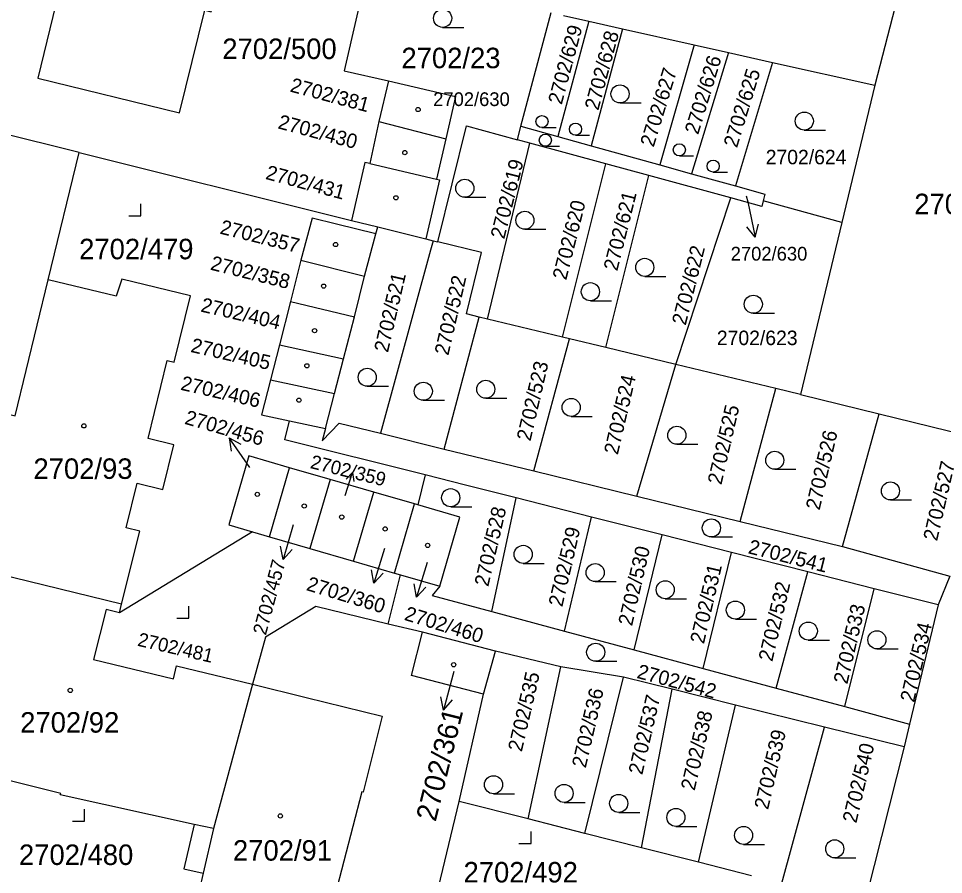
# Model space of a CAD drawing. Extents: x -496682 to -495776, y -1088797 to -1088018.
# Drawn here: x -496634.1 to -496557.4, y -1088522.6 to -1088451.6 of the extents above; entities that cross this region are included whole.
import ezdxf

# ---------------------------------------------------------------- set-up
doc = ezdxf.new("R2010")
doc.units = 0
for name, color, linetype in [('Hranice parcel', 7, 'Continuous'), ('Parcelní čísla', 7, 'Continuous'), ('Pop  PČ popisy', 7, 'Continuous'), ('Vnitřní kresba', 7, 'Continuous'), ('Značky budov', 7, 'Continuous'), ('Značky kultur', 7, 'Continuous')]:
    doc.layers.add(name, color=color, linetype=linetype)

msp = doc.modelspace()

# ---------------------------------------------------------------- linework, layer by layer
at = {"layer": 'Hranice parcel'}
for p, q in [((-496560.5, -1088447.06), (-496563.11, -1088457.17)), ((-496592.45, -1088460.57), (-496589.94, -1088451.12)), ((-496586.83, -1088451.86), (-496589.39, -1088461.42)), ((-496588.92, -1088451.39), (-496586.83, -1088451.86)), ((-496586.83, -1088451.86), (-496584.04, -1088452.48)), ((-496584.04, -1088452.48), (-496586.63, -1088462.19)), ((-496584.04, -1088452.48), (-496578.08, -1088453.82)), ((-496578.08, -1088453.82), (-496580.92, -1088463.77)), ((-496578.08, -1088453.82), (-496575.25, -1088454.45)), ((-496575.25, -1088454.45), (-496578.3, -1088464.51)), ((-496575.25, -1088454.45), (-496571.59, -1088455.27)), ((-496571.59, -1088455.27), (-496574.67, -1088465.51)), ((-496571.59, -1088455.27), (-496563.11, -1088457.17)), ((-496603.42, -1088456.81), (-496604.23, -1088460.18)), ((-496563.11, -1088457.17), (-496565.84, -1088468.56)), ((-496629.09, -1088462.74), (-496640.95, -1088459.81)), ((-496604.23, -1088460.18), (-496604.99, -1088463.66)), ((-496604.23, -1088460.18), (-496598.69, -1088461.62)), ((-496592.74, -1088461.68), (-496592.45, -1088460.57)), ((-496592.45, -1088460.57), (-496589.39, -1088461.42)), ((-496598.69, -1088461.62), (-496599.45, -1088464.96)), ((-496591.72, -1088461.96), (-496592.74, -1088461.68)), ((-496589.39, -1088461.42), (-496586.63, -1088462.19)), ((-496595.21, -1088476.56), (-496591.72, -1088461.96)), ((-496585.42, -1088463.68), (-496591.72, -1088461.96)), ((-496586.63, -1088462.19), (-496580.92, -1088463.77)), ((-496631.65, -1088473.31), (-496629.09, -1088462.74)), ((-496604.99, -1088463.66), (-496599.45, -1088464.96)), ((-496589.01, -1088478.06), (-496585.42, -1088463.68)), ((-496581.84, -1088464.65), (-496585.42, -1088463.68)), ((-496580.92, -1088463.77), (-496578.3, -1088464.51)), ((-496585.4, -1088478.93), (-496581.84, -1088464.65)), ((-496575.06, -1088466.51), (-496581.84, -1088464.65)), ((-496578.3, -1088464.51), (-496574.67, -1088465.51)), ((-496579.62, -1088480.33), (-496575.06, -1088466.51)), ((-496565.84, -1088468.56), (-496572.37, -1088466.76)), ((-496606.49, -1088468.38), (-496604.32, -1088468.92)), ((-496565.84, -1088468.56), (-496569.26, -1088482.83)), ((-496605.41, -1088472.99), (-496604.48, -1088469.49)), ((-496604.48, -1088469.49), (-496604.32, -1088468.92)), ((-496604.32, -1088468.92), (-496600.33, -1088469.91)), ((-496600.33, -1088469.91), (-496599.74, -1088470.06)), ((-496599.74, -1088470.06), (-496599.34, -1088470.16)), ((-496610.7, -1088471.68), (-496611.55, -1088475.11)), ((-496610.7, -1088471.68), (-496605.41, -1088472.99)), ((-496606.26, -1088476.38), (-496605.41, -1088472.99)), ((-496611.55, -1088475.11), (-496612.47, -1088478.69)), ((-496611.55, -1088475.11), (-496606.26, -1088476.38)), ((-496607.16, -1088479.85), (-496606.26, -1088476.38)), ((-496598.81, -1088487.34), (-496595.91, -1088476.39)), ((-496595.21, -1088476.56), (-496595.91, -1088476.39)), ((-496589.01, -1088478.06), (-496595.21, -1088476.56)), ((-496612.47, -1088478.69), (-496613.22, -1088481.59)), ((-496612.47, -1088478.69), (-496607.16, -1088479.85)), ((-496591.38, -1088489.16), (-496588.43, -1088478.2)), ((-496588.43, -1088478.2), (-496589.01, -1088478.06)), ((-496585.4, -1088478.93), (-496588.43, -1088478.2)), ((-496579.62, -1088480.33), (-496585.4, -1088478.93)), ((-496607.91, -1088482.74), (-496607.16, -1088479.85)), ((-496582.83, -1088491.26), (-496579.62, -1088480.33)), ((-496571.31, -1088482.33), (-496579.62, -1088480.33)), ((-496613.22, -1088481.59), (-496607.91, -1088482.74)), ((-496574.26, -1088493.36), (-496571.31, -1088482.33)), ((-496569.26, -1088482.83), (-496571.31, -1088482.33)), ((-496608.66, -1088485.64), (-496607.91, -1088482.74)), ((-496569.26, -1088482.83), (-496562.76, -1088484.43)), ((-496565.8, -1088495.44), (-496562.76, -1088484.43)), ((-496562.76, -1088484.43), (-496553.34, -1088486.74)), ((-496611.65, -1088485), (-496608.66, -1088485.64)), ((-496608.66, -1088485.64), (-496608.93, -1088486.67)), ((-496604.09, -1088486.04), (-496598.81, -1088487.34)), ((-496611.65, -1088488.89), (-496615.02, -1088487.91)), ((-496598.81, -1088487.34), (-496591.38, -1088489.16)), ((-496613.31, -1088494.62), (-496611.65, -1088488.89)), ((-496608.28, -1088489.87), (-496611.65, -1088488.89)), ((-496600.4, -1088489.48), (-496601.01, -1088491.98)), ((-496591.38, -1088489.16), (-496582.83, -1088491.26)), ((-496608.28, -1088489.87), (-496609.94, -1088495.6)), ((-496604.66, -1088490.92), (-496608.28, -1088489.87)), ((-496606.33, -1088496.65), (-496604.66, -1088490.92)), ((-496601.27, -1088491.9), (-496604.66, -1088490.92)), ((-496594.87, -1088500.81), (-496592.84, -1088491.4)), ((-496586.59, -1088492.99), (-496592.84, -1088491.4)), ((-496582.83, -1088491.26), (-496574.26, -1088493.36)), ((-496602.94, -1088497.63), (-496601.27, -1088491.9)), ((-496601.01, -1088491.98), (-496601.27, -1088491.9)), ((-496588.84, -1088502.44), (-496586.59, -1088492.99)), ((-496580.73, -1088494.47), (-496586.59, -1088492.99)), ((-496574.26, -1088493.36), (-496565.8, -1088495.44)), ((-496614.7, -1088494.21), (-496625.74, -1088500.93)), ((-496614.7, -1088494.21), (-496613.31, -1088494.62)), ((-496613.31, -1088494.62), (-496609.94, -1088495.6)), ((-496583.05, -1088504), (-496580.73, -1088494.47)), ((-496574.99, -1088495.93), (-496580.73, -1088494.47)), ((-496609.94, -1088495.6), (-496606.33, -1088496.65)), ((-496565.8, -1088495.44), (-496556.89, -1088497.88)), ((-496577.33, -1088505.54), (-496574.99, -1088495.93)), ((-496568.66, -1088497.54), (-496574.99, -1088495.93)), ((-496606.33, -1088496.65), (-496602.94, -1088497.63)), ((-496625.56, -1088500.2), (-496637.35, -1088497.34)), ((-496603.45, -1088501.86), (-496602.44, -1088497.78)), ((-496602.94, -1088497.63), (-496602.44, -1088497.78)), ((-496602.44, -1088497.78), (-496599.17, -1088498.73)), ((-496571.29, -1088507.17), (-496568.66, -1088497.54)), ((-496563.16, -1088498.94), (-496568.66, -1088497.54)), ((-496556.89, -1088497.88), (-496557.86, -1088500.28)), ((-496599.17, -1088498.73), (-496599.81, -1088499.48)), ((-496599.81, -1088499.48), (-496594.87, -1088500.81)), ((-496565.6, -1088508.71), (-496563.16, -1088498.94)), ((-496557.86, -1088500.28), (-496563.16, -1088498.94)), ((-496625.74, -1088500.93), (-496625.56, -1088500.2)), ((-496594.87, -1088500.81), (-496588.84, -1088502.44)), ((-496557.86, -1088500.28), (-496560.22, -1088510.16)), ((-496600.61, -1088502.54), (-496603.45, -1088501.86)), ((-496594.55, -1088504.11), (-496600.61, -1088502.54)), ((-496588.84, -1088502.44), (-496583.05, -1088504)), ((-496583.05, -1088504), (-496577.33, -1088505.54)), ((-496595.56, -1088507.68), (-496594.55, -1088504.11)), ((-496589.15, -1088505.41), (-496594.55, -1088504.11)), ((-496591.86, -1088518.03), (-496589.15, -1088505.41)), ((-496583.95, -1088506.27), (-496589.15, -1088505.41)), ((-496577.33, -1088505.54), (-496571.29, -1088507.17)), ((-496587.14, -1088519.23), (-496583.95, -1088506.27)), ((-496579.92, -1088507.27), (-496583.95, -1088506.27)), ((-496597.58, -1088516.58), (-496595.56, -1088507.68)), ((-496582.44, -1088520.43), (-496579.92, -1088507.27)), ((-496574.65, -1088508.58), (-496579.92, -1088507.27)), ((-496571.29, -1088507.17), (-496565.6, -1088508.71)), ((-496577.74, -1088521.62), (-496574.65, -1088508.58)), ((-496567.27, -1088510.42), (-496574.65, -1088508.58)), ((-496565.6, -1088508.71), (-496560.22, -1088510.16)), ((-496560.22, -1088510.16), (-496560.68, -1088512.06)), ((-496570.83, -1088523.36), (-496567.27, -1088510.42)), ((-496560.68, -1088512.06), (-496567.27, -1088510.42)), ((-496560.68, -1088512.06), (-496563.91, -1088524.85)), ((-496601.3, -1088532.22), (-496597.58, -1088516.58)), ((-496591.86, -1088518.03), (-496597.58, -1088516.58)), ((-496587.14, -1088519.23), (-496591.86, -1088518.03)), ((-496582.44, -1088520.43), (-496587.14, -1088519.23)), ((-496577.74, -1088521.62), (-496582.44, -1088520.43)), ((-496573.34, -1088522.74), (-496577.74, -1088521.62))]:
    msp.add_line(p, q, dxfattribs=at)
for points in [[(-496627.19, -1088437.45), (-496629.65, -1088447.47), (-496630.27, -1088447.33), (-496632.51, -1088456.57), (-496620.75, -1088459.46), (-496618.65, -1088450.94), (-496618.13, -1088451.06), (-496617.25, -1088447.52), (-496617.78, -1088447.42), (-496615.79, -1088439.35)], [(-496605.08, -1088447.17), (-496607.1, -1088455.97), (-496603.42, -1088456.81)], [(-496603.42, -1088456.81), (-496597.88, -1088458.09), (-496598.69, -1088461.62)], [(-496599.34, -1088470.16), (-496596.95, -1088460.53), (-496592.74, -1088461.68)], [(-496629.09, -1088462.74), (-496607.59, -1088468.1), (-496606.49, -1088468.38)], [(-496604.99, -1088463.66), (-496605.38, -1088463.57), (-496606.49, -1088468.38)], [(-496599.45, -1088464.96), (-496599.21, -1088465.01), (-496600.33, -1088469.91)], [(-496574.67, -1088465.51), (-496572.24, -1088466.19), (-496572.37, -1088466.76)], [(-496572.37, -1088466.76), (-496572.48, -1088467.21), (-496575.06, -1088466.51)], [(-496604.48, -1088469.49), (-496607.73, -1088468.68), (-496609.76, -1088468.18), (-496610.7, -1088471.68)], [(-496599.74, -1088470.06), (-496599.96, -1088470.85), (-496604.09, -1088486.04)], [(-496595.91, -1088476.39), (-496596.96, -1088476.14), (-496595.73, -1088471.05), (-496599.34, -1088470.16)], [(-496637.35, -1088497.34), (-496634.78, -1088486.77), (-496635.48, -1088486.6), (-496634.95, -1088484.46), (-496634.38, -1088484.6), (-496631.65, -1088473.31)], [(-496625.56, -1088500.2), (-496624.06, -1088494.16), (-496625.17, -1088493.89), (-496624.28, -1088490.18), (-496622.15, -1088490.71), (-496621.22, -1088487), (-496623.35, -1088486.47), (-496621.79, -1088479.99), (-496621.21, -1088480.13), (-496619.86, -1088474.64), (-496625.54, -1088473.24), (-496626, -1088474.67), (-496631.65, -1088473.31)], [(-496613.22, -1088481.59), (-496613.97, -1088484.5), (-496611.65, -1088485)], [(-496600.4, -1088489.48), (-496612.03, -1088486.58), (-496611.65, -1088485)], [(-496608.93, -1088486.67), (-496607.51, -1088485.21), (-496604.09, -1088486.04)], [(-496615.02, -1088487.91), (-496616.68, -1088493.64), (-496614.7, -1088494.21)], [(-496592.84, -1088491.4), (-496597.04, -1088490.33), (-496600.4, -1088489.48)], [(-496599.17, -1088498.73), (-496597.51, -1088493), (-496601.01, -1088491.98)], [(-496625.74, -1088500.93), (-496626.84, -1088500.66), (-496627.88, -1088504.8), (-496621.27, -1088506.42), (-496621, -1088505.32), (-496614.7, -1088506.86)], [(-496603.45, -1088501.86), (-496609.45, -1088500.4), (-496613.64, -1088502.94), (-496614.7, -1088506.86)], [(-496595.56, -1088507.68), (-496601.53, -1088506.12), (-496600.61, -1088502.54)], [(-496614.7, -1088506.86), (-496617.94, -1088518.83), (-496619.55, -1088518.48)], [(-496619.55, -1088518.48), (-496630.64, -1088516.04), (-496630.61, -1088515.92), (-496641.69, -1088513.15), (-496641.66, -1088513.05)], [(-496619.55, -1088518.48), (-496620.39, -1088522.17), (-496618.8, -1088522.54), (-496620.02, -1088527.84), (-496620.32, -1088527.76), (-496621.75, -1088533.36)]]:
    msp.add_lwpolyline(points, dxfattribs=at)
at = {"layer": 'Pop  PČ popisy'}
for p, q in [((-496573.77, -1088466.34), (-496573.65, -1088466.84)), ((-496573.65, -1088466.84), (-496573.026, -1088469.775)), ((-496573.026, -1088469.775), (-496572.744, -1088468.692)), ((-496573.026, -1088469.775), (-496573.724, -1088468.9)), ((-496614.93, -1088488.87), (-496616.651, -1088486.412)), ((-496616.651, -1088486.412), (-496615.667, -1088486.945)), ((-496616.651, -1088486.412), (-496616.487, -1088487.519)), ((-496607.03, -1088491.21), (-496606.409, -1088489.298)), ((-496606.409, -1088489.298), (-496606.935, -1088489.832)), ((-496606.409, -1088489.298), (-496606.297, -1088490.04)), ((-496611.34, -1088493.63), (-496612.167, -1088496.515)), ((-496612.167, -1088496.515), (-496612.372, -1088495.414)), ((-496603.77, -1088495.59), (-496604.647, -1088498.46)), ((-496612.167, -1088496.515), (-496611.41, -1088495.69)), ((-496600.23, -1088496.75), (-496601.107, -1088499.62)), ((-496604.647, -1088498.46), (-496604.833, -1088497.356)), ((-496604.647, -1088498.46), (-496603.876, -1088497.649)), ((-496601.107, -1088499.62), (-496601.293, -1088498.516)), ((-496601.107, -1088499.62), (-496600.336, -1088498.809)), ((-496598.1, -1088506.1), (-496598.877, -1088508.999)), ((-496598.02, -1088505.81), (-496598.1, -1088506.1)), ((-496598.877, -1088508.999), (-496599.101, -1088507.902)), ((-496598.877, -1088508.999), (-496598.134, -1088508.161))]:
    msp.add_line(p, q, dxfattribs=at)
at = {"layer": 'Vnitřní kresba'}
for p, q in [((-496614.7, -1088506.86), (-496610.25, -1088507.95)), ((-496610.25, -1088507.95), (-496603.96, -1088509.5)), ((-496603.96, -1088509.5), (-496605.52, -1088515.81)), ((-496605.65, -1088515.77), (-496609.45, -1088530.51)), ((-496605.52, -1088515.81), (-496605.65, -1088515.77)), ((-496617.94, -1088518.83), (-496618.8, -1088522.54))]:
    msp.add_line(p, q, dxfattribs=at)
at = {"layer": 'Značky budov'}
for centre in [(-496600.977, -1088459.179), (-496602.077, -1088462.749), (-496602.817, -1088466.499), (-496607.817, -1088470.379), (-496608.807, -1088473.829), (-496609.557, -1088477.519), (-496610.197, -1088480.439), (-496610.857, -1088483.289), (-496628.687, -1088485.419), (-496614.307, -1088491.099), (-496610.417, -1088492.069), (-496607.307, -1088492.989), (-496603.707, -1088493.969), (-496600.187, -1088495.339), (-496598.027, -1088505.239), (-496629.817, -1088507.369), (-496612.397, -1088517.779)]:
    msp.add_circle(centre, 0.175, dxfattribs=at)
at = {"layer": 'Značky kultur'}
for p, q in [((-496598.943, -1088452.36), (-496597.193, -1088452.36)), ((-496584.233, -1088458.63), (-496582.483, -1088458.63)), ((-496590.705, -1088460.68), (-496589.533, -1088460.68)), ((-496568.953, -1088460.89), (-496567.203, -1088460.89)), ((-496587.925, -1088461.31), (-496586.753, -1088461.31)), ((-496590.425, -1088462.22), (-496589.253, -1088462.22)), ((-496579.315, -1088463.02), (-496578.143, -1088463.02)), ((-496576.505, -1088464.37), (-496575.333, -1088464.37)), ((-496597.103, -1088466.46), (-496595.353, -1088466.46)), ((-496623.96, -1088468.01), (-496623.96, -1088467.01)), ((-496624.961, -1088468.01), (-496623.96, -1088468.01)), ((-496592.123, -1088469.11), (-496590.373, -1088469.11)), ((-496582.183, -1088473.02), (-496580.433, -1088473.02)), ((-496586.693, -1088475.04), (-496584.943, -1088475.04)), ((-496573.183, -1088476.08), (-496571.433, -1088476.08)), ((-496605.193, -1088482.14), (-496603.443, -1088482.14)), ((-496600.543, -1088483.3), (-496598.793, -1088483.3)), ((-496595.363, -1088483.13), (-496593.613, -1088483.13)), ((-496588.283, -1088484.64), (-496586.533, -1088484.64)), ((-496579.523, -1088486.95), (-496577.773, -1088486.95)), ((-496571.403, -1088489.02), (-496569.653, -1088489.02)), ((-496561.813, -1088491.57), (-496560.063, -1088491.57)), ((-496598.273, -1088492.13), (-496596.523, -1088492.13)), ((-496576.663, -1088494.64), (-496574.913, -1088494.64)), ((-496592.263, -1088496.83), (-496590.513, -1088496.83)), ((-496586.293, -1088498.34), (-496584.543, -1088498.34)), ((-496580.483, -1088499.77), (-496578.733, -1088499.77)), ((-496619.98, -1088501.37), (-496619.98, -1088500.37)), ((-496620.981, -1088501.37), (-496619.98, -1088501.37)), ((-496574.673, -1088501.45), (-496572.923, -1088501.45)), ((-496568.623, -1088503.2), (-496566.873, -1088503.2)), ((-496562.933, -1088503.92), (-496561.183, -1088503.92)), ((-496586.253, -1088504.95), (-496584.503, -1088504.95)), ((-496594.723, -1088515.94), (-496592.973, -1088515.94)), ((-496588.873, -1088516.66), (-496587.123, -1088516.66)), ((-496628.63, -1088518.21), (-496628.63, -1088517.21)), ((-496584.343, -1088517.49), (-496582.593, -1088517.49)), ((-496629.631, -1088518.21), (-496628.63, -1088518.21)), ((-496579.603, -1088518.65), (-496577.853, -1088518.65)), ((-496591.61, -1088520.06), (-496591.61, -1088519.06)), ((-496592.611, -1088520.06), (-496591.61, -1088520.06)), ((-496573.993, -1088520.15), (-496572.243, -1088520.15)), ((-496566.433, -1088521.26), (-496564.683, -1088521.26))]:
    msp.add_line(p, q, dxfattribs=at)
for centre, radius in [((-496598.943, -1088451.61), 0.75), ((-496584.233, -1088457.88), 0.75), ((-496568.953, -1088460.14), 0.75), ((-496590.705, -1088460.177), 0.502), ((-496587.925, -1088460.807), 0.502), ((-496590.425, -1088461.717), 0.502), ((-496579.315, -1088462.517), 0.502), ((-496576.505, -1088463.867), 0.502), ((-496597.103, -1088465.71), 0.75), ((-496592.123, -1088468.36), 0.75), ((-496582.183, -1088472.27), 0.75), ((-496586.693, -1088474.29), 0.75), ((-496573.183, -1088475.33), 0.75), ((-496605.193, -1088481.39), 0.75), ((-496600.543, -1088482.55), 0.75), ((-496595.363, -1088482.38), 0.75), ((-496588.283, -1088483.89), 0.75), ((-496579.523, -1088486.2), 0.75), ((-496571.403, -1088488.27), 0.75), ((-496561.813, -1088490.82), 0.75), ((-496598.273, -1088491.38), 0.75), ((-496576.663, -1088493.89), 0.75), ((-496592.263, -1088496.08), 0.75), ((-496586.293, -1088497.59), 0.75), ((-496580.483, -1088499.02), 0.75), ((-496574.673, -1088500.7), 0.75), ((-496568.623, -1088502.45), 0.75), ((-496562.933, -1088503.17), 0.75), ((-496586.253, -1088504.2), 0.75), ((-496594.723, -1088515.19), 0.75), ((-496588.873, -1088515.91), 0.75), ((-496584.343, -1088516.74), 0.75), ((-496579.603, -1088517.9), 0.75), ((-496573.993, -1088519.4), 0.75), ((-496566.433, -1088520.51), 0.75)]:
    msp.add_circle(centre, radius, dxfattribs=at)

# ---------------------------------------------------------------- texts
at = {"layer": 'Parcelní čísla'}
for s, height, rotation, p in [('2702/629', 1.2, 75, (-496589.068, -1088458.825)), ('2702/628', 1.2, 75, (-496586.038, -1088459.305)), ('2702/626', 1.2, 73, (-496577.758, -1088461.315)), ('2702/627', 1.2, 73, (-496581.448, -1088462.355)), ('2702/625', 1.2, 73, (-496574.538, -1088462.415)), ('2702/381', 1.2, 345, (-496611.658, -1088457.677)), ('2702/430', 1.2, 345, (-496612.668, -1088460.727)), ('2702/619', 1.2, 76, (-496593.834, -1088469.978)), ('2702/431', 1.2, 345, (-496613.688, -1088464.927)), ('2702/621', 1.2, 76, (-496584.464, -1088472.628)), ('2702/620', 1.2, 76, (-496588.694, -1088473.378)), ('2702/357', 1.2, 346, (-496617.475, -1088469.463)), ('2702/622', 1.2, 76, (-496578.794, -1088477.138)), ('2702/358', 1.2, 346, (-496618.265, -1088472.453)), ('2702/521', 1.2, 77, (-496603.479, -1088479.39)), ('2702/522', 1.2, 77, (-496598.469, -1088479.63)), ('2702/404', 1.2, 347, (-496619.06, -1088475.93)), ('2702/405', 1.2, 347, (-496619.89, -1088479.28)), ('2702/523', 1.2, 77, (-496591.659, -1088486.74)), ('2702/406', 1.2, 347, (-496620.73, -1088482.42)), ('2702/524', 1.2, 77, (-496584.419, -1088487.87)), ('2702/456', 1.2, 344, (-496620.401, -1088485.24)), ('2702/525', 1.2, 77, (-496575.829, -1088490.36)), ('2702/526', 1.2, 77, (-496567.689, -1088492.47)), ('2702/359', 1.139, 346, (-496609.98, -1088488.912)), ('2702/527', 1.2, 77, (-496557.949, -1088495.03)), ('2702/528', 1.2, 77, (-496595.159, -1088498.81)), ('2702/529', 1.2, 77, (-496589.019, -1088500.49)), ('2702/541', 1.2, 346, (-496573.678, -1088495.985)), ('2702/530', 1.2, 77, (-496583.239, -1088502.08)), ('2702/457', 1.139, 75, (-496613.601, -1088502.844)), ('2702/531', 1.2, 77, (-496577.279, -1088503.56)), ('2702/360', 1.2, 343, (-496610.312, -1088499.034)), ('2702/532', 1.2, 77, (-496571.609, -1088505.03)), ('2702/533', 1.2, 77, (-496565.389, -1088506.9)), ('2702/460', 1.2, 343, (-496602.192, -1088501.504)), ('2702/534', 1.2, 77, (-496559.859, -1088508.41)), ('2702/481', 1.139, 347, (-496624.301, -1088503.656)), ('2702/542', 1.2, 345, (-496582.905, -1088506.321)), ('2702/535', 1.2, 77, (-496592.379, -1088512.51)), ('2702/536', 1.2, 77, (-496587.079, -1088513.86)), ('2702/537', 1.2, 77, (-496582.389, -1088514.42)), ('2702/361', 1.7, 76, (-496599.522, -1088518.316)), ('2702/538', 1.2, 77, (-496578.049, -1088515.73)), ('2702/539', 1.2, 77, (-496571.959, -1088517.31)), ('2702/540', 1.2, 77, (-496564.639, -1088518.43))]:
    msp.add_text(s, height=height, rotation=rotation, dxfattribs=at).set_placement(p)
for s, height, p in [('2702/500', 1.7, (-496617.21, -1088454.99)), ('2702/23', 1.7, (-496602.358, -1088455.75)), ('2702/630', 1.139, (-496599.728, -1088458.889)), ('2702/624', 1.2, (-496572.155, -1088463.72)), ('2702/97', 1.7, (-496559.838, -1088467.86)), ('2702/479', 1.7, (-496629.08, -1088471.6)), ('2702/630', 1.139, (-496575.058, -1088471.709)), ('2702/623', 1.2, (-496576.205, -1088478.72)), ('2702/93', 1.7, (-496632.868, -1088489.82)), ('2702/92', 1.7, (-496633.968, -1088510.87)), ('2702/480', 1.7, (-496634.07, -1088521.85)), ('2702/91', 1.7, (-496616.328, -1088521.49)), ('2702/492', 1.7, (-496597.21, -1088523.3))]:
    msp.add_text(s, height=height, dxfattribs=at).set_placement(p)

doc.saveas('drawing.dxf')
